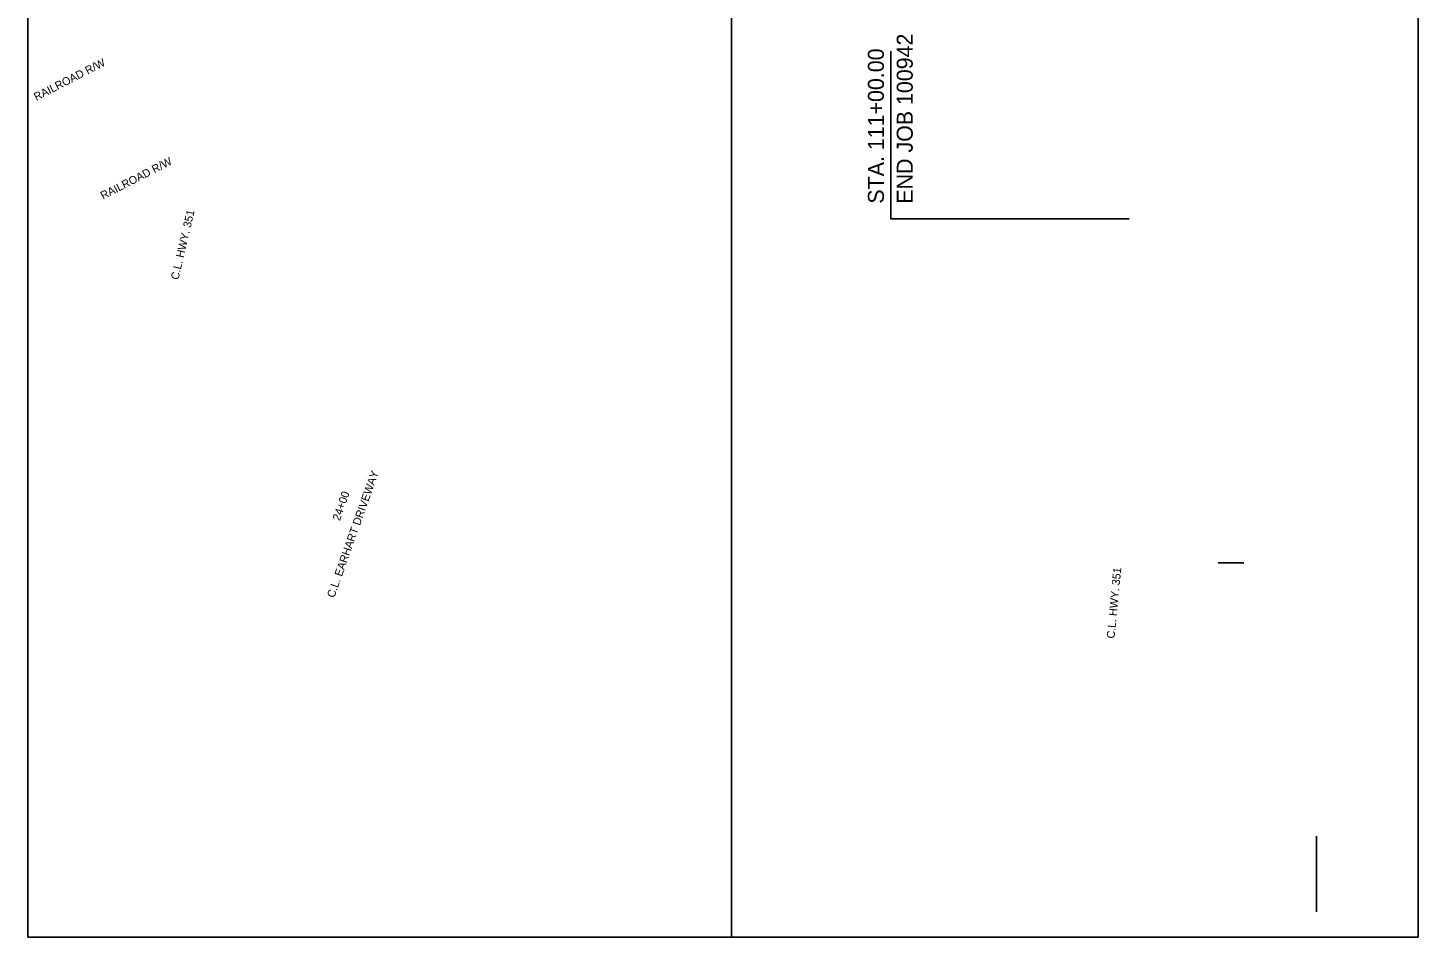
# Model space of a CAD drawing. Extents: x 1712161 to 1713203, y 549259 to 550855.
# Drawn here: x 1712161 to 1713203, y 549259 to 549941 of the extents above; entities that cross this region are included whole.
import ezdxf

# ---------------------------------------------------------------- set-up
doc = ezdxf.new("R2010")
doc.units = 0
for name, color, linetype in [('Default', 7, 'Continuous'), ('R_Horz Alg Annot', 7, 'Continuous'), ('R_Proposed Const Limits_Fill', 7, 'Continuous')]:
    doc.layers.add(name, color=color, linetype=linetype)

msp = doc.modelspace()

# ---------------------------------------------------------------- linework, layer by layer
at = {"layer": 'Default'}
msp.add_lwpolyline([(1712361.5, 550854.5), (1712688.2, 550854.5), (1712688.2, 549259.2), (1712160.6, 549259.2), (1712160.6, 550443.2), (1712210, 550443.2), (1712210, 550620.8), (1712227.8, 550620.8), (1712227.8, 550639), (1712224.6, 550639), (1712224.6, 550716.7)], dxfattribs=at)
msp.add_lwpolyline([(1712361.5, 550854.5), (1712688.2, 550854.5), (1712688.2, 549259.2), (1712160.6, 549259.2), (1712160.6, 550443.2), (1712210, 550443.2), (1712210, 550620.8), (1712227.8, 550620.8), (1712227.8, 550639), (1712224.6, 550639), (1712224.6, 550716.7)], dxfattribs=at)
msp.add_lwpolyline([(1712361.5, 550854.5), (1712688.2, 550854.5), (1712688.2, 549259.2), (1712160.6, 549259.2), (1712160.6, 550443.2), (1712210, 550443.2), (1712210, 550620.8), (1712227.8, 550620.8), (1712227.8, 550639), (1712224.6, 550639), (1712224.6, 550716.7)], dxfattribs=at)
msp.add_lwpolyline([(1712361.5, 550854.5), (1712688.2, 550854.5), (1712688.2, 549259.2), (1712160.6, 549259.2), (1712160.6, 550443.2), (1712210, 550443.2), (1712210, 550620.8), (1712227.8, 550620.8), (1712227.8, 550639), (1712224.6, 550639), (1712224.6, 550716.7)], dxfattribs=at)
msp.add_lwpolyline([(1712361.5, 550854.5), (1712688.2, 550854.5), (1712688.2, 549259.2), (1712160.6, 549259.2), (1712160.6, 550443.2), (1712210, 550443.2), (1712210, 550620.8), (1712227.8, 550620.8), (1712227.8, 550639), (1712224.6, 550639), (1712224.6, 550716.7)], dxfattribs=at)
msp.add_lwpolyline([(1712361.5, 550854.5), (1712688.2, 550854.5), (1712688.2, 549259.2), (1712160.6, 549259.2), (1712160.6, 550443.2), (1712210, 550443.2), (1712210, 550620.8), (1712227.8, 550620.8), (1712227.8, 550639), (1712224.6, 550639), (1712224.6, 550716.7)], dxfattribs=at)
msp.add_lwpolyline([(1712361.5, 550854.5), (1712688.2, 550854.5), (1712688.2, 549259.2), (1712160.6, 549259.2), (1712160.6, 550443.2), (1712210, 550443.2), (1712210, 550620.8), (1712227.8, 550620.8), (1712227.8, 550639), (1712224.6, 550639), (1712224.6, 550716.7)], dxfattribs=at)
msp.add_lwpolyline([(1712361.5, 550854.5), (1712688.2, 550854.5), (1712688.2, 549259.2), (1712160.6, 549259.2), (1712160.6, 550443.2), (1712210, 550443.2), (1712210, 550620.8), (1712227.8, 550620.8), (1712227.8, 550639), (1712224.6, 550639), (1712224.6, 550716.7)], dxfattribs=at)
msp.add_lwpolyline([(1712688.2, 549259.2), (1712688.2, 550854.5), (1713202.9, 550854.5), (1713202.9, 549259.2)], close=True, dxfattribs=at)
msp.add_lwpolyline([(1712688.2, 549259.2), (1712688.2, 550854.5), (1713202.9, 550854.5), (1713202.9, 549259.2)], close=True, dxfattribs=at)
msp.add_lwpolyline([(1712688.2, 549259.2), (1712688.2, 550854.5), (1713202.9, 550854.5), (1713202.9, 549259.2)], close=True, dxfattribs=at)
msp.add_lwpolyline([(1712688.2, 549259.2), (1712688.2, 550854.5), (1713202.9, 550854.5), (1713202.9, 549259.2)], close=True, dxfattribs=at)
msp.add_lwpolyline([(1712688.2, 549259.2), (1712688.2, 550854.5), (1713202.9, 550854.5), (1713202.9, 549259.2)], close=True, dxfattribs=at)
msp.add_lwpolyline([(1712688.2, 549259.2), (1712688.2, 550854.5), (1713202.9, 550854.5), (1713202.9, 549259.2)], close=True, dxfattribs=at)
at = {"layer": 'R_Horz Alg Annot'}
for p, q in [((1712688.2, 549755.8), (1712688.2, 549946.5)), ((1712688.2, 549259.2), (1712688.2, 549755.8)), ((1713052.9, 549540.1), (1713072.3, 549539.9))]:
    msp.add_line(p, q, dxfattribs=at)
msp.add_lwpolyline([(1712986.3, 549798), (1712807.6, 549798), (1712807.6, 549923.8)], dxfattribs=at)
at = {"layer": 'R_Proposed Const Limits_Fill'}
msp.add_line((1713126.7, 549278.3), (1713126.7, 549334.9), dxfattribs=at)

# ---------------------------------------------------------------- texts
at = {"layer": 'R_Horz Alg Annot'}
for s, height, rotation, p in [('END JOB 100942', 12, 90, (1712824, 549809.4)), ('RAILROAD R/W', 6, 27.2066, (1712167, 549886.4)), ('STA. 111+00.00', 12, 90, (1712802.4, 549809.4)), ('RAILROAD R/W', 6, 27.2066, (1712217, 549812.3)), ('C.L. HWY. 351', 6, 76.7828, (1712273.5, 549751.9)), ('C.L. EARHART DRIVEWAY', 6, 70.4957, (1712390.3, 549513.3)), ('24+00', 6, 70.7734, (1712394.5, 549571.1)), ('C.L. HWY. 351', 6, 84.5388, (1712975.3, 549483))]:
    msp.add_text(s, height=height, rotation=rotation, dxfattribs=at).set_placement(p)

doc.saveas('drawing.dxf')
